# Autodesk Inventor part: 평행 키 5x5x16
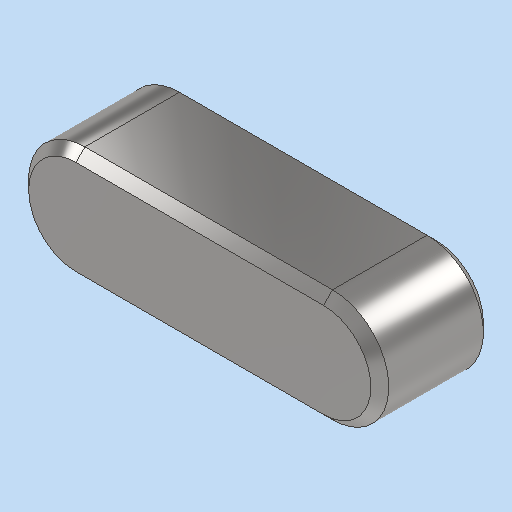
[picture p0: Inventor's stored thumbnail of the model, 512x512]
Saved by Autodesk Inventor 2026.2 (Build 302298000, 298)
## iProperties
Created: 2026-01
Part Number: 평행 키 5x5x16
Material: 강철, 연강
Description: 키 및 해당 키홈
Document SubType Name: Modeling
Designer: PC2-07
Density: 7.85 g/cm^3
Appearance: 기본값
Author: jhkim
Sending System: Autodesk Inventor 2026
Preprocessor: ST-DEVELOPER v20.1
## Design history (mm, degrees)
feature "Solid1"
node "솔리드1"
